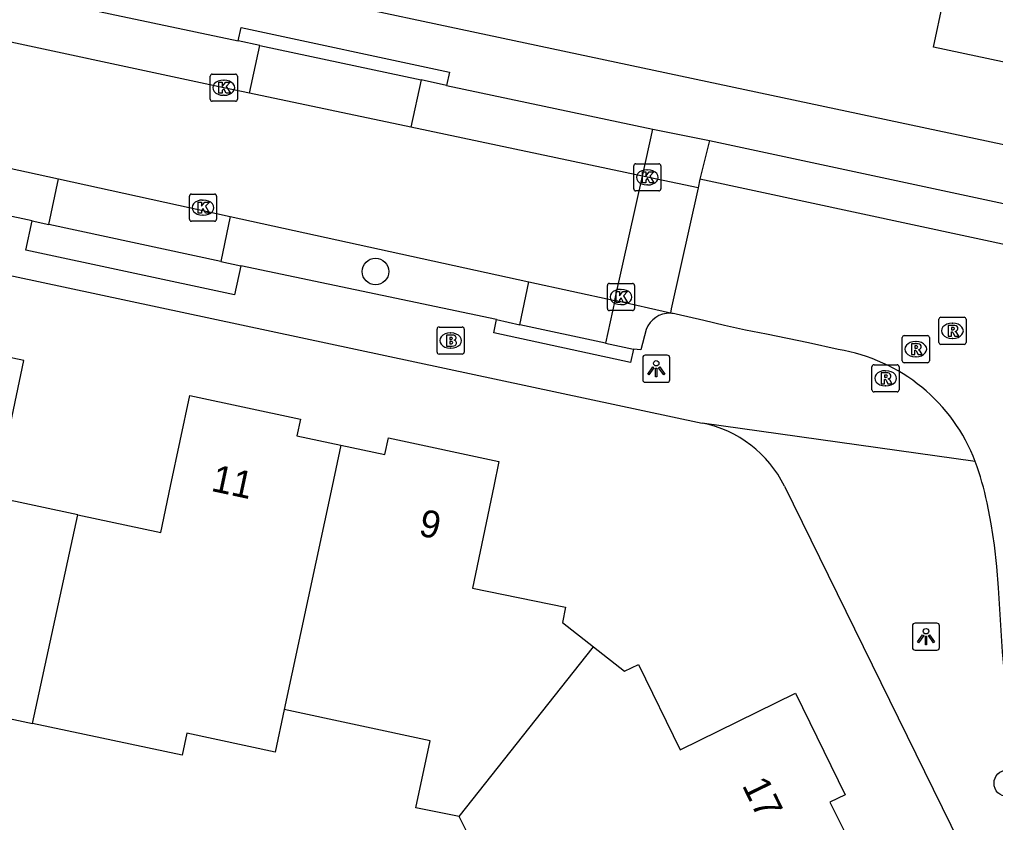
# Model space of a CAD drawing. Extents: x 160457 to 162082, y 388340 to 389736.
# Drawn here: x 160791.15 to 160827.09, y 388987.6 to 389017.2 of the extents above; entities that cross this region are included whole.
import ezdxf

# ---------------------------------------------------------------- set-up
doc = ezdxf.new("R2010")
doc.units = 0
for name, color, linetype in [('IMGEO_Boom', 7, 'Continuous'), ('IMGEO_Brandkraan', 7, 'Continuous'), ('IMGEO_Kolk', 7, 'Continuous'), ('IMGEO_Lichtpunt', 7, 'Continuous'), ('IMGEO_Pand', 7, 'Continuous'), ('IMGEO_Pand_nummerreeks', 7, 'Continuous'), ('IMGEO_Parkeervlak_open', 7, 'Continuous'), ('IMGEO_Rijbaan_lokaal_gesloten', 7, 'Continuous'), ('IMGEO_Rijbaan_lokaal_open', 7, 'Continuous'), ('IMGEO_Rioolput', 7, 'Continuous'), ('IMGEO_Voetpad_open', 7, 'Continuous')]:
    doc.layers.add(name, color=color, linetype=linetype)

msp = doc.modelspace()

# ---------------------------------------------------------------- linework, layer by layer
at = {"layer": 'IMGEO_Boom'}
for centre in [(160804.256, 389007.908), (160827.525, 388989.046)]:
    msp.add_circle(centre, 0.489, dxfattribs=at)
at = {"layer": 'IMGEO_Brandkraan'}
for p, q in [((160806.523, 389004.937), (160806.523, 389005.789)), ((160806.598, 389005.863), (160807.45, 389005.863)), ((160807.524, 389005.789), (160807.524, 389004.937)), ((160807.011, 389005.643), (160807.036, 389005.643)), ((160807.034, 389005.083), (160807.009, 389005.083)), ((160807.45, 389004.863), (160806.598, 389004.863))]:
    msp.add_line(p, q, dxfattribs=at)
for points in [[(160806.523, 389004.937), (160806.523, 389005.789)], [(160806.598, 389005.863), (160807.45, 389005.863)], [(160807.524, 389005.789), (160807.524, 389004.937)], [(160806.871, 389005.563), (160806.871, 389005.163), (160807.084, 389005.163)], [(160807.102, 389005.563), (160806.871, 389005.563)], [(160807.05, 389005.482), (160806.996, 389005.482), (160806.996, 389005.406)], [(160806.996, 389005.406), (160807.049, 389005.406)], [(160807.058, 389005.33), (160806.996, 389005.33), (160806.996, 389005.249)], [(160806.996, 389005.249), (160807.058, 389005.249)], [(160807.45, 389004.863), (160806.598, 389004.863)]]:
    msp.add_lwpolyline(points, dxfattribs=at)
for centre, radius, start, end in [((160806.6, 389005.787), 0.0765, 91.552, 178.448), ((160806.6, 389005.787), 0.0765, 91.552, 178.448), ((160807.448, 389005.787), 0.0765, 1.552, 88.448), ((160807.448, 389005.787), 0.0765, 1.552, 88.448), ((160807.051, 389005.444), 0.0379, 267.8285, 90.9355), ((160807.106, 389005.418), 0.145, 59.4692, 91.5367), ((160807.131, 389005.465), 0.0922, 285.5137, 58.1501), ((160807.136, 389005.273), 0.105, 301.3115, 78.989), ((160807.059, 389005.289), 0.0404, 269.8759, 90.5077), ((160807.09, 389005.414), 0.251, 268.6676, 293.5347), ((160806.6, 389004.939), 0.0765, 181.552, 268.448), ((160806.6, 389004.939), 0.0765, 181.552, 268.448), ((160807.448, 389004.939), 0.0765, 271.552, 358.448), ((160807.448, 389004.939), 0.0765, 271.552, 358.448)]:
    msp.add_arc(centre, radius, start, end, dxfattribs=at)
for centre, major_axis, ratio, start_param, end_param in [((160807.01, 389005.363), (-0.387, 0.002), 0.722429, 4.712389, 7.853982), ((160807.035, 389005.363), (-0.39, 0.002), 0.717154, 1.570796, 4.712389)]:
    msp.add_ellipse(centre, major_axis=major_axis, ratio=ratio, start_param=start_param, end_param=end_param, dxfattribs=at)
at = {"layer": 'IMGEO_Kolk'}
for p, q in [((160798.169, 389014.256), (160798.169, 389015.108)), ((160798.244, 389015.182), (160799.096, 389015.182)), ((160799.17, 389015.108), (160799.17, 389014.256)), ((160798.657, 389014.962), (160798.682, 389014.962)), ((160798.68, 389014.402), (160798.655, 389014.402)), ((160799.096, 389014.182), (160798.244, 389014.182)), ((160813.766, 389010.953), (160813.766, 389011.805)), ((160813.841, 389011.879), (160814.693, 389011.879)), ((160814.767, 389011.805), (160814.767, 389010.953)), ((160814.254, 389011.659), (160814.279, 389011.659)), ((160814.277, 389011.099), (160814.252, 389011.099)), ((160797.478, 389010.762), (160798.33, 389010.762)), ((160814.693, 389010.879), (160813.841, 389010.879)), ((160797.403, 389009.836), (160797.403, 389010.688)), ((160797.891, 389010.542), (160797.916, 389010.542)), ((160798.404, 389010.688), (160798.404, 389009.836)), ((160798.33, 389009.762), (160797.478, 389009.762)), ((160797.914, 389009.982), (160797.889, 389009.982)), ((160812.796, 389006.543), (160812.796, 389007.395)), ((160812.871, 389007.469), (160813.723, 389007.469)), ((160813.284, 389007.249), (160813.309, 389007.249)), ((160813.797, 389007.395), (160813.797, 389006.543)), ((160813.723, 389006.469), (160812.871, 389006.469)), ((160813.307, 389006.689), (160813.282, 389006.689))]:
    msp.add_line(p, q, dxfattribs=at)
for points in [[(160798.169, 389014.256), (160798.169, 389015.108)], [(160798.244, 389015.182), (160799.096, 389015.182)], [(160799.17, 389015.108), (160799.17, 389014.256)], [(160798.49, 389014.882), (160798.613, 389014.882), (160798.613, 389014.731), (160798.743, 389014.882), (160798.907, 389014.882), (160798.761, 389014.731), (160798.914, 389014.482), (160798.762, 389014.482), (160798.677, 389014.646), (160798.613, 389014.579), (160798.613, 389014.482), (160798.49, 389014.482), (160798.49, 389014.882)], [(160799.096, 389014.182), (160798.244, 389014.182)], [(160813.766, 389010.953), (160813.766, 389011.805)], [(160813.841, 389011.879), (160814.693, 389011.879)], [(160814.767, 389011.805), (160814.767, 389010.953)], [(160814.087, 389011.579), (160814.21, 389011.579), (160814.21, 389011.428), (160814.34, 389011.579), (160814.504, 389011.579), (160814.358, 389011.428), (160814.511, 389011.179), (160814.359, 389011.179), (160814.274, 389011.343), (160814.21, 389011.276), (160814.21, 389011.179), (160814.087, 389011.179), (160814.087, 389011.579)], [(160797.478, 389010.762), (160798.33, 389010.762)], [(160814.693, 389010.879), (160813.841, 389010.879)], [(160797.403, 389009.836), (160797.403, 389010.688)], [(160797.724, 389010.462), (160797.847, 389010.462), (160797.847, 389010.311), (160797.977, 389010.462), (160798.141, 389010.462), (160797.995, 389010.311), (160798.148, 389010.062), (160797.996, 389010.062), (160797.911, 389010.226), (160797.847, 389010.159), (160797.847, 389010.062), (160797.724, 389010.062), (160797.724, 389010.462)], [(160798.404, 389010.688), (160798.404, 389009.836)], [(160798.33, 389009.762), (160797.478, 389009.762)], [(160812.796, 389006.543), (160812.796, 389007.395)], [(160812.871, 389007.469), (160813.723, 389007.469)], [(160813.117, 389007.169), (160813.24, 389007.169), (160813.24, 389007.018), (160813.37, 389007.169), (160813.534, 389007.169), (160813.388, 389007.018), (160813.541, 389006.769), (160813.389, 389006.769), (160813.304, 389006.933), (160813.24, 389006.866), (160813.24, 389006.769), (160813.117, 389006.769), (160813.117, 389007.169)], [(160813.797, 389007.395), (160813.797, 389006.543)], [(160813.723, 389006.469), (160812.871, 389006.469)]]:
    msp.add_lwpolyline(points, dxfattribs=at)
for centre, start, end in [((160798.246, 389015.106), 91.552, 178.448), ((160798.246, 389015.106), 91.552, 178.448), ((160799.094, 389015.106), 1.552, 88.448), ((160799.094, 389015.106), 1.552, 88.448), ((160798.246, 389014.258), 181.552, 268.448), ((160798.246, 389014.258), 181.552, 268.448), ((160799.094, 389014.258), 271.552, 358.448), ((160799.094, 389014.258), 271.552, 358.448), ((160813.843, 389011.803), 91.552, 178.448), ((160813.843, 389011.803), 91.552, 178.448), ((160814.691, 389011.803), 1.552, 88.448), ((160814.691, 389011.803), 1.552, 88.448), ((160797.48, 389010.686), 91.552, 178.448), ((160797.48, 389010.686), 91.552, 178.448), ((160798.328, 389010.686), 1.552, 88.448), ((160798.328, 389010.686), 1.552, 88.448), ((160813.843, 389010.955), 181.552, 268.448), ((160813.843, 389010.955), 181.552, 268.448), ((160814.691, 389010.955), 271.552, 358.448), ((160814.691, 389010.955), 271.552, 358.448), ((160797.48, 389009.838), 181.552, 268.448), ((160797.48, 389009.838), 181.552, 268.448), ((160798.328, 389009.838), 271.552, 358.448), ((160798.328, 389009.838), 271.552, 358.448), ((160812.873, 389007.393), 91.552, 178.448), ((160812.873, 389007.393), 91.552, 178.448), ((160813.721, 389007.393), 1.552, 88.448), ((160813.721, 389007.393), 1.552, 88.448), ((160812.873, 389006.545), 181.552, 268.448), ((160812.873, 389006.545), 181.552, 268.448), ((160813.721, 389006.545), 271.552, 358.448), ((160813.721, 389006.545), 271.552, 358.448)]:
    msp.add_arc(centre, 0.0765, start, end, dxfattribs=at)
for centre, major_axis, ratio, start_param, end_param in [((160798.656, 389014.682), (-0.387, 0.002), 0.722429, 4.712389, 7.853982), ((160798.681, 389014.682), (-0.39, 0.002), 0.717154, 1.570796, 4.712389), ((160814.253, 389011.379), (-0.387, 0.002), 0.722429, 4.712389, 7.853982), ((160814.278, 389011.379), (-0.39, 0.002), 0.717154, 1.570796, 4.712389), ((160797.89, 389010.262), (-0.387, 0.002), 0.722429, 4.712389, 7.853982), ((160797.915, 389010.262), (-0.39, 0.002), 0.717154, 1.570796, 4.712389), ((160813.283, 389006.969), (-0.387, 0.002), 0.722429, 4.712389, 7.853982), ((160813.308, 389006.969), (-0.39, 0.002), 0.717154, 1.570796, 4.712389)]:
    msp.add_ellipse(centre, major_axis=major_axis, ratio=ratio, start_param=start_param, end_param=end_param, dxfattribs=at)
at = {"layer": 'IMGEO_Lichtpunt'}
for p, q in [((160814.098, 389004.728), (160814.098, 389003.921)), ((160814.098, 389004.728), (160814.098, 389003.921)), ((160815, 389004.823), (160814.192, 389004.823)), ((160815, 389004.823), (160814.192, 389004.823)), ((160815.094, 389003.921), (160815.094, 389004.728)), ((160815.094, 389003.921), (160815.094, 389004.728)), ((160814.192, 389003.827), (160815, 389003.827)), ((160814.192, 389003.827), (160815, 389003.827)), ((160824.933, 388994.949), (160824.125, 388994.949)), ((160824.933, 388994.949), (160824.125, 388994.949)), ((160824.031, 388994.854), (160824.031, 388994.047)), ((160824.031, 388994.854), (160824.031, 388994.047)), ((160825.027, 388994.047), (160825.027, 388994.854)), ((160825.027, 388994.047), (160825.027, 388994.854)), ((160824.125, 388993.953), (160824.933, 388993.953)), ((160824.125, 388993.953), (160824.933, 388993.953))]:
    msp.add_line(p, q, dxfattribs=at)
for points in [[(160814.472, 389004.392), (160814.511, 389004.364), (160814.323, 389004.102), (160814.285, 389004.129), (160814.472, 389004.392)], [(160814.574, 389004.344), (160814.621, 389004.344), (160814.621, 389004.022), (160814.574, 389004.022), (160814.574, 389004.344)], [(160814.684, 389004.364), (160814.722, 389004.391), (160814.909, 389004.129), (160814.87, 389004.101), (160814.684, 389004.364)], [(160824.405, 388994.518), (160824.444, 388994.49), (160824.256, 388994.228), (160824.218, 388994.255), (160824.405, 388994.518)], [(160824.507, 388994.47), (160824.554, 388994.47), (160824.554, 388994.148), (160824.507, 388994.148), (160824.507, 388994.47)], [(160824.617, 388994.49), (160824.655, 388994.517), (160824.842, 388994.255), (160824.803, 388994.227), (160824.617, 388994.49)]]:
    msp.add_lwpolyline(points, dxfattribs=at)
for centre in [(160814.597, 389004.526), (160824.53, 388994.652)]:
    msp.add_circle(centre, 0.0994, dxfattribs=at)
for centre, start, end in [((160814.192, 389004.728), 90, 180), ((160814.192, 389004.728), 90, 180), ((160815, 389004.728), 0, 90), ((160815, 389004.728), 0, 90), ((160814.192, 389003.921), 180, 270), ((160814.192, 389003.921), 180, 270), ((160815, 389003.921), 270, 0), ((160815, 389003.921), 270, 360), ((160824.125, 388994.854), 90, 180), ((160824.125, 388994.854), 90, 180), ((160824.933, 388994.854), 0, 90), ((160824.933, 388994.854), 0, 90), ((160824.125, 388994.047), 180, 270), ((160824.125, 388994.047), 180, 270), ((160824.933, 388994.047), 270, 0), ((160824.933, 388994.047), 270, 360)]:
    msp.add_arc(centre, 0.0946, start, end, dxfattribs=at)
at = {"layer": 'IMGEO_Pand'}
for points in [[(160830.644, 389015.588), (160829.031, 389015.926), (160828.901, 389015.303), (160824.81, 389016.181), (160825.877, 389021.203), (160822.819, 389021.853)], [(160793.296, 388998.943), (160790.239, 388999.592), (160790.325, 389000), (160791.305, 389004.63), (160787.235, 389005.485), (160787.106, 389004.869), (160785.491, 389005.216)], [(160793.296, 388998.943), (160796.352, 388998.294), (160796.713, 389000), (160797.421, 389003.341), (160801.495, 389002.469), (160801.363, 389001.853), (160802.983, 389001.506)], [(160802.983, 389001.506), (160804.599, 389001.159), (160804.731, 389001.775), (160808.797, 389000.903), (160808.61, 389000), (160807.831, 388996.24), (160811.254, 388995.532), (160811.143, 388994.973), (160812.281, 388994.076)], [(160802.983, 389001.506), (160802.66, 389000), (160800.895, 388991.768)], [(160791.629, 388991.252), (160793.296, 388998.943)], [(160783.081, 388994.004), (160786.317, 388993.314), (160786.127, 388992.425), (160791.629, 388991.252)], [(160807.341, 388987.818), (160812.281, 388994.076)], [(160812.281, 388994.076), (160813.426, 388993.174), (160813.938, 388993.424), (160815.475, 388990.279), (160819.73, 388992.368), (160821.557, 388988.625), (160820.99, 388988.349), (160821.732, 388986.849)], [(160800.895, 388991.768), (160800.559, 388990.195), (160797.305, 388990.889), (160797.132, 388990.078), (160791.629, 388991.252)], [(160807.341, 388987.818), (160805.743, 388988.141), (160806.273, 388990.615), (160800.895, 388991.768)], [(160812.793, 388982.487), (160810.372, 388981.306), (160807.944, 388986.221), (160808.094, 388986.294), (160807.341, 388987.818)]]:
    msp.add_lwpolyline(points, dxfattribs=at)
at = {"layer": 'IMGEO_Parkeervlak_open'}
for points in [[(160799.619, 389014.48), (160799.992, 389016.243)], [(160805.933, 389014.967), (160805.564, 389013.223)], [(160814.084, 389011.421), (160814.475, 389013.157)], [(160816.553, 389012.731), (160816.207, 389011.308)], [(160792.23, 389009.642), (160792.588, 389011.325)], [(160798.91, 389009.941), (160798.557, 389008.282)], [(160809.571, 389005.949), (160809.908, 389007.534)], [(160813.068, 389006.842), (160812.733, 389005.266)]]:
    msp.add_lwpolyline(points, dxfattribs=at)
at = {"layer": 'IMGEO_Rijbaan_lokaal_gesloten'}
for points in [[(160799.619, 389014.48), (160798.67, 389014.681), (160788.58, 389016.839)], [(160805.564, 389013.223), (160799.619, 389014.48)], [(160781.228, 389013.811), (160792.588, 389011.325)], [(160814.084, 389011.421), (160805.564, 389013.223)], [(160792.588, 389011.325), (160798.91, 389009.941)], [(160816.207, 389011.308), (160816.135, 389010.987)], [(160843.699, 389005.404), (160816.207, 389011.308)], [(160816.135, 389010.987), (160815.141, 389006.537), (160815.115, 389006.368)], [(160798.91, 389009.941), (160809.908, 389007.534)], [(160809.908, 389007.534), (160813.068, 389006.842)], [(160821.296, 389005.033), (160820.207, 389005.28), (160819.433, 389005.444), (160818.656, 389005.597), (160817.881, 389005.751), (160817.11, 389005.915), (160816.346, 389006.099), (160815.329, 389006.335)], [(160827.59, 388992.046), (160827.533, 388992.317), (160827.423, 388993.1), (160827.349, 388993.886), (160827.297, 388994.674), (160827.252, 388995.463), (160827.202, 388996.252), (160827.138, 388997.04), (160827.051, 388997.824), (160826.934, 388998.605), (160826.781, 388999.38)]]:
    msp.add_lwpolyline(points, dxfattribs=at)
for centre, radius, start, end in [((160815.087, 389005.474), 0.894, 74.2815, 88.186), ((160820.245, 388998.598), 6.52, 20.6841, 80.7235), ((160814.926, 388996.805), 12.132, 12.2561, 19.7342)]:
    msp.add_arc(centre, radius, start, end, dxfattribs=at)
at = {"layer": 'IMGEO_Rijbaan_lokaal_open'}
for points in [[(160813.068, 389006.842), (160813.108, 389007.028), (160814.084, 389011.421)], [(160816.135, 389010.987), (160814.084, 389011.421)], [(160815.115, 389006.368), (160813.068, 389006.842)]]:
    msp.add_lwpolyline(points, dxfattribs=at)
at = {"layer": 'IMGEO_Rioolput'}
for p, q in [((160825.003, 389005.297), (160825.003, 389006.149)), ((160825.078, 389006.223), (160825.93, 389006.223)), ((160826.004, 389006.149), (160826.004, 389005.297)), ((160825.491, 389006.003), (160825.516, 389006.003)), ((160823.653, 389004.621), (160823.653, 389005.473)), ((160823.728, 389005.547), (160824.58, 389005.547)), ((160824.654, 389005.473), (160824.654, 389004.621)), ((160825.514, 389005.443), (160825.489, 389005.443)), ((160824.141, 389005.327), (160824.166, 389005.327)), ((160825.93, 389005.223), (160825.078, 389005.223)), ((160824.164, 389004.767), (160824.139, 389004.767)), ((160822.54, 389003.546), (160822.54, 389004.398)), ((160822.615, 389004.472), (160823.467, 389004.472)), ((160823.541, 389004.398), (160823.541, 389003.546)), ((160824.58, 389004.547), (160823.728, 389004.547)), ((160823.028, 389004.252), (160823.053, 389004.252)), ((160823.051, 389003.692), (160823.026, 389003.692)), ((160823.467, 389003.472), (160822.615, 389003.472))]:
    msp.add_line(p, q, dxfattribs=at)
for points in [[(160825.003, 389005.297), (160825.003, 389006.149)], [(160825.078, 389006.223), (160825.93, 389006.223)], [(160826.004, 389006.149), (160826.004, 389005.297)], [(160825.592, 389005.921), (160825.34, 389005.923), (160825.34, 389005.523)], [(160825.518, 389005.842), (160825.464, 389005.842), (160825.464, 389005.761)], [(160825.464, 389005.761), (160825.516, 389005.761)], [(160823.653, 389004.621), (160823.653, 389005.473)], [(160823.728, 389005.547), (160824.58, 389005.547)], [(160824.654, 389005.473), (160824.654, 389004.621)], [(160825.34, 389005.523), (160825.464, 389005.523), (160825.464, 389005.685), (160825.475, 389005.685)], [(160825.522, 389005.656), (160825.593, 389005.523), (160825.733, 389005.523), (160825.668, 389005.649)], [(160824.242, 389005.245), (160823.99, 389005.247), (160823.99, 389004.847)], [(160823.99, 389004.847), (160824.114, 389004.847), (160824.114, 389005.009), (160824.125, 389005.009)], [(160824.168, 389005.166), (160824.114, 389005.166), (160824.114, 389005.085)], [(160824.114, 389005.085), (160824.166, 389005.085)], [(160824.172, 389004.98), (160824.243, 389004.847), (160824.383, 389004.847), (160824.318, 389004.973)], [(160825.93, 389005.223), (160825.078, 389005.223)], [(160822.54, 389003.546), (160822.54, 389004.398)], [(160822.615, 389004.472), (160823.467, 389004.472)], [(160823.541, 389004.398), (160823.541, 389003.546)], [(160824.58, 389004.547), (160823.728, 389004.547)], [(160823.129, 389004.17), (160822.877, 389004.172), (160822.877, 389003.772)], [(160822.877, 389003.772), (160823.001, 389003.772), (160823.001, 389003.934), (160823.012, 389003.934)], [(160823.055, 389004.091), (160823.001, 389004.091), (160823.001, 389004.01)], [(160823.001, 389004.01), (160823.053, 389004.01)], [(160823.059, 389003.905), (160823.13, 389003.772), (160823.27, 389003.772), (160823.205, 389003.898)], [(160823.467, 389003.472), (160822.615, 389003.472)]]:
    msp.add_lwpolyline(points, dxfattribs=at)
for centre, radius, start, end in [((160825.08, 389006.147), 0.0765, 91.552, 178.448), ((160825.08, 389006.147), 0.0765, 91.552, 178.448), ((160825.928, 389006.147), 0.0765, 1.552, 88.448), ((160825.928, 389006.147), 0.0765, 1.552, 88.448), ((160825.5, 389005.95), 0.19, 274.7715, 282.9687), ((160825.524, 389005.746), 0.0964, 77.0061, 93.1865), ((160825.538, 389005.803), 0.0378, 276.6634, 79.6772), ((160825.591, 389005.811), 0.109, 350.3612, 89.416), ((160825.589, 389005.811), 0.112, 277.5842, 350.9817), ((160825.573, 389005.596), 0.108, 29.5134, 73.7905), ((160823.73, 389005.471), 0.0765, 91.552, 178.448), ((160823.73, 389005.471), 0.0765, 91.552, 178.448), ((160824.578, 389005.471), 0.0765, 1.552, 88.448), ((160824.578, 389005.471), 0.0765, 1.552, 88.448), ((160825.474, 389005.632), 0.0533, 26.0293, 88.6989), ((160824.124, 389004.956), 0.0533, 26.0293, 88.6989), ((160824.15, 389005.274), 0.19, 274.7715, 282.9687), ((160824.174, 389005.07), 0.0964, 77.0061, 93.1865), ((160824.188, 389005.127), 0.0378, 276.6634, 79.6772), ((160824.241, 389005.135), 0.109, 350.3612, 89.416), ((160824.239, 389005.135), 0.112, 277.5842, 350.9817), ((160824.223, 389004.92), 0.108, 29.5134, 73.7905), ((160825.08, 389005.299), 0.0765, 181.552, 268.448), ((160825.08, 389005.299), 0.0765, 181.552, 268.448), ((160825.928, 389005.299), 0.0765, 271.552, 358.448), ((160825.928, 389005.299), 0.0765, 271.552, 358.448), ((160823.73, 389004.623), 0.0765, 181.552, 268.448), ((160823.73, 389004.623), 0.0765, 181.552, 268.448), ((160824.578, 389004.623), 0.0765, 271.552, 358.448), ((160824.578, 389004.623), 0.0765, 271.552, 358.448), ((160822.617, 389004.396), 0.0765, 91.552, 178.448), ((160822.617, 389004.396), 0.0765, 91.552, 178.448), ((160823.465, 389004.396), 0.0765, 1.552, 88.448), ((160823.465, 389004.396), 0.0765, 1.552, 88.448), ((160823.011, 389003.881), 0.0533, 26.0293, 88.6989), ((160823.037, 389004.199), 0.19, 274.7715, 282.9687), ((160823.061, 389003.995), 0.0964, 77.0061, 93.1865), ((160823.075, 389004.052), 0.0378, 276.6634, 79.6772), ((160823.128, 389004.06), 0.109, 350.3612, 89.416), ((160823.126, 389004.06), 0.112, 277.5842, 350.9817), ((160823.11, 389003.845), 0.108, 29.5134, 73.7905), ((160822.617, 389003.548), 0.0765, 181.552, 268.448), ((160822.617, 389003.548), 0.0765, 181.552, 268.448), ((160823.465, 389003.548), 0.0765, 271.552, 358.448), ((160823.465, 389003.548), 0.0765, 271.552, 358.448)]:
    msp.add_arc(centre, radius, start, end, dxfattribs=at)
for centre, major_axis, ratio, start_param, end_param in [((160825.49, 389005.723), (-0.387, 0.002), 0.722429, 4.712389, 7.853982), ((160825.515, 389005.723), (-0.39, 0.002), 0.717154, 1.570796, 4.712389), ((160824.14, 389005.047), (-0.387, 0.002), 0.722429, 4.712389, 7.853982), ((160824.165, 389005.047), (-0.39, 0.002), 0.717154, 1.570796, 4.712389), ((160823.027, 389003.972), (-0.387, 0.002), 0.722429, 4.712389, 7.853982), ((160823.052, 389003.972), (-0.39, 0.002), 0.717154, 1.570796, 4.712389)]:
    msp.add_ellipse(centre, major_axis=major_axis, ratio=ratio, start_param=start_param, end_param=end_param, dxfattribs=at)
at = {"layer": 'IMGEO_Voetpad_open'}
for points in [[(160851.028, 389007.553), (160759.604, 389027.003)], [(160789.765, 389018.409), (160799.2, 389016.413)], [(160799.2, 389016.413), (160799.304, 389016.901), (160806.98, 389015.253), (160806.876, 389014.765)], [(160799.992, 389016.243), (160799.2, 389016.413)], [(160799.992, 389016.243), (160805.933, 389014.967)], [(160756.984, 389014.991), (160816.292, 389002.325)], [(160806.876, 389014.765), (160805.933, 389014.967)], [(160806.876, 389014.765), (160814.475, 389013.157)], [(160814.475, 389013.157), (160816.553, 389012.731)], [(160816.553, 389012.731), (160828.933, 389010.089), (160844.001, 389006.893)], [(160791.615, 389009.774), (160781.877, 389011.851)], [(160799.298, 389008.123), (160799.067, 389007.048), (160791.384, 389008.699), (160791.615, 389009.774)], [(160791.615, 389009.774), (160792.23, 389009.642)], [(160798.557, 389008.282), (160792.23, 389009.642)], [(160798.557, 389008.282), (160799.298, 389008.123)], [(160808.716, 389006.134), (160799.298, 389008.123)], [(160813.758, 389005.045), (160813.653, 389004.557), (160808.611, 389005.646), (160808.716, 389006.134)], [(160808.716, 389006.134), (160809.571, 389005.949)], [(160812.733, 389005.266), (160809.571, 389005.949)], [(160814.226, 389005.773), (160814.025, 389005.016), (160813.758, 389005.045)], [(160812.733, 389005.266), (160813.758, 389005.045)], [(160826.345, 389000.901), (160816.292, 389002.325)], [(160819.315, 389000), (160825.449, 388987.505), (160869.221, 388897.954)]]:
    msp.add_lwpolyline(points, dxfattribs=at)
for centre, radius, start, end in [((160815.083, 389005.454), 0.914, 87.9988, 159.5893), ((160815.44, 388998.089), 4.321, 26.2475, 78.6245)]:
    msp.add_arc(centre, radius, start, end, dxfattribs=at)

# ---------------------------------------------------------------- texts
at = {"layer": 'IMGEO_Pand_nummerreeks'}
for s, rotation, p in [('11', 347.9187, (160798.165, 388999.828)), ('9', 347.8956, (160805.807, 388998.189)), ('17', 296.0808, (160817.74, 388988.973))]:
    msp.add_text(s, height=1, rotation=rotation, dxfattribs=at).set_placement(p)

doc.saveas('drawing.dxf')
